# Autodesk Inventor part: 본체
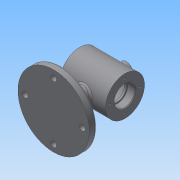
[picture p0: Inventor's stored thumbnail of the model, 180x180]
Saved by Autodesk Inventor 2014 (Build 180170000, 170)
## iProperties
Created: 2018-12
Part Number: 본체
Material: 일반
Document SubType Name: Modeling
Designer: net
Density: 1 g/cm^3
Appearance: 기본값
Author: net
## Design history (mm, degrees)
sketch "스케치1"
  geometry: L1 (-35, 0)-(35, 0); L2 (-35, 0)-(-35, 30); L3 (-35, 30)-(35, 30); L4 (35, 30)-(35, 0); L5 (-35, 16)-(-23, 16); L6 (-23, 16)-(-23, 14); L7 (-23, 14)-(-20, 14); L8 (-20, 14)-(-20, 25); L9 (-20, 25)-(20, 25); L10 (20, 25)-(20, 14); L11 (20, 14)-(23, 14); L12 (23, 14)-(23, 16); L13 (23, 16)-(35, 16); 2 further points
  constraints: 26 end point, 6 parallel, 5 perpendicular, 2 horizontal alignment, 2 point on line, 1 coincident, 1 collinear, 1 horizontal, 1 midpoint
  dimensions: "d0" = 70 distance of L1.start L1.end; "d1" = 60 diameter of L3 L1; "d2" = 50 diameter of L9 L1; "d3" = 28 diameter of L7 L1; "d4" = 32 diameter of L5 L1; "d5" = 40 distance between parallel lines of L10 L8; "d6" = 12 distance of L5.start L5.end; "d7" = 12 distance of L12.end L13.end; "d8" = 3 distance of L6.end L7.end
revolve "회전1" sketch "스케치1" stored, may be unused: angle "d9" = 90 deg
fillet "모깎기1" dims "d10" = 0.3
fillet "모깎기2" dims "d11" = 3
chamfer "모따기1" distance "d12" = 1; stored, may be unused: second distance "d13" = 2, angle "d14" = 45 deg
sketch "스케치2" dims "d15" = 46
  geometry: C1 r 30 at (0, 0) reference; C2 r 17 at (0, 0) reference; 2 further points
  constraints: 2 vertical alignment, 1 coincident, 2 other
hole "구멍1" sketch "스케치2" at (0, 23) diameter "d16" = 3.242; stored, may be unused: countersink angle "d20" = 90 deg, drill point angle "d22" = 118 deg; dims "d17" = 8, "d18" = 4, "d19" = 2, "d21" = 10
node "작업 평면1"
sketch "스케치3"
  geometry: C1 r 10 at (0, 0); 1 further point
  constraints: 1 centre point, 1 coincident
  dimensions: "d27" = 20 diameter of C1
extrude "돌출1" join sketch "스케치3" stored distance "d28" = 10; taper "d29" = 0 deg
fillet "모깎기3" dims "d30" = 3
sketch "스케치4"
  geometry: C1 r 10 at (0, 0) reference; C2 r 5 at (0, 0)
  constraints: 1 centre point, 1 coincident
  dimensions: "d31" = 10 diameter of C2
extrude "돌출2" cut sketch "스케치4" stored distance "d32" = 10; taper "d33" = 0 deg
chamfer "모따기2" distance "d34" = 1; stored, may be unused: second distance "d35" = 2, angle "d36" = 45 deg
node "작업 평면2"
sketch "스케치6"
  geometry: L1 (0, 0)-(-75, 0); L2 (-75, 0)-(-75, -55); L3 (-75, -55)-(-64, -55); L4 (-64, -55)-(-49.263, 0); L5 (-49.263, 0)-(-75, 0); L6 (-64, -55)-(-64, 7.013)
  constraints: 12 end point, 4 perpendicular, 1 horizontal, 1 point on line
  dimensions: "d41" = 75 distance of L1.start L1.end; "d42" = 55 distance of L1.end L2.end; "d43" = 11 distance of L2.end L3.end; "d44" = 75 deg angle of L3 L4
revolve "회전2" sketch "스케치6" stored, may be unused: angle "d45" = 90 deg
fillet "모깎기4" dims "d46" = 3
sketch "스케치7"
  geometry: C1 r 55 at (0, 0) reference
node "작업 평면3"
sketch "스케치8"
  geometry: C1 r 12 at (0, 0); 1 further point
  constraints: 1 centre point, 1 coincident
  dimensions: "d47" = 24 diameter of C1
extrude "돌출4" join sketch "스케치8" stored distance "d48" = 2; taper "d49" = 0 deg
sketch "스케치9"
  geometry: C1 r 12 at (0, 0); A1 r 12 centre (0, 0) between (12, 0) and (-12, 0) reference; A2 r 12 centre (0, 0) between (-12, 0) and (12, 0) reference
  constraints: 1 centre point, 1 coincident, 1 concentric
extrude "돌출5" join sketch "스케치9" stored distance "d50" = 2; taper "d51" = 0 deg
fillet "모깎기5" dims "d52" = 3
sketch "스케치10" dims "d53" = 88
  geometry: C1 r 55 at (0, 0) reference; C2 r 4.5 at (0, 44); 1 further point
  constraints: 2 vertical alignment, 1 centre point, 1 coincident, 2 other
  dimensions: "d54" = 9 diameter of C2
extrude "돌출6" cut sketch "스케치10" distance "d55" = 10; taper "d56" = 0 deg
sketch "스케치11"
  geometry: C1 r 4.5 at (0, 0) reference; C2 r 7 at (0, 0); 1 further point
  constraints: 1 centre point, 1 coincident
  dimensions: "d57" = 14 diameter of C2
extrude "돌출7" cut sketch "스케치11" distance "d58" = 20; taper "d59" = 0 deg
sketch "스케치12"
  geometry: C1 r 4.5 at (0, 0) reference; C2 r 4.5 at (0, 0); 1 further point
  constraints: 1 centre point, 1 coincident, 1 concentric
extrude "돌출8" cut sketch "스케치12" distance "d60" = 20; taper "d61" = 0 deg
sketch "스케치13"
  geometry: C1 r 4.5 at (0, 0) reference; C2 r 4.5 at (0, 0); C3 r 4.5 at (-44, -44) reference; C4 r 4.5 at (-44, -44); C5 r 4.5 at (-88, 0) reference; C6 r 4.5 at (-88, 0); 1 further point
  constraints: 3 centre point, 3 coincident, 3 concentric
extrude "돌출9" cut sketch "스케치13" distance "d65" = 20; taper "d66" = 0 deg
fillet "모깎기6" dims "d67" = 3
node "작업 평면4"
sketch "스케치14"
  geometry: L1 (-35, 30)-(35, 30) reference; L2 (-35, -30)-(-35, 30) reference; 2 further points
  constraints: 1 other
  dimensions: "d69" = 30 distance from line of L1 point (0, 0); "d70" = 35 distance from line of point (0, 0) L2
feature "엠보싱1" sketch "스케치14" dims "d71" = 0.5, "d72" = 0
node "솔리드1"
pattern_circular "원형 패턴1" dims angle "d24" = 360 deg
mirror "대칭1"
pattern_circular "원형 패턴2" dims angle "d63" = 360 deg
other parameters: "d26" = 37, "d37" = -75
